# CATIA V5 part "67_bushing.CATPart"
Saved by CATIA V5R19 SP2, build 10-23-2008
Part number: 67_bushing
Bounding box of the stored display mesh (mm): x -20.495 to 20.495, y 119.884 to 160.84, z -4.564 to 26.936
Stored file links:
  C:\Documents and Settings\anizard\Bureau\13\67_bushing.CATPart
  C:\Program Files (x86)\Dassault Systemes\B19\intel_a\reffiles\standard\MetricThickPitch.txt
  C:\Documents and Settings\anizard\Bureau\13\anizard.CATProduct
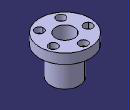
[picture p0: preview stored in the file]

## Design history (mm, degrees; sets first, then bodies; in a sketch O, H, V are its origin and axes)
Set1
  Line1: linked copy from another document
  Point1 to Point4: linked copy from another document
  Plane1 to Plane3: linked copy from another document
Body1 (main body)
  Sketch1 on yz-plane, origin (0, 0, 0), H (0, 1, 0), V (0, 0, 1)
    line L1 (160.8619, 26.936) -> (160.8619, 18.936)
    line L2 (160.8619, 18.936) -> (152.1119, 18.936)
    line L3 (152.1119, 18.936) -> (152.1119, -4.564)
    line L4 (152.1119, -4.564) -> (140.3619, -4.564)
    line L5 (160.8619, 26.936) -> (140.3619, 26.936)
    line L6 (140.3619, 26.936) -> (140.3619, -4.564)
    reference projected point E1 (152.1119, 18.936) from Point1
    reference projected point E2 (160.8619, 18.936) from Point2
    reference projected line E3 (140.3619, -341.064) -> (140.3619, 38.936) from Line1
    reference intersected line E4 through (0, 26.936) direction (-1, 0) from Plane1
    reference intersected line E5 through (0, 18.936) direction (-1, 0) from Plane2
    reference intersected line E6 through (0, -4.564) direction (-1, 0) from Plane3
    vertical: L1 V, L3 V, L6 V
    horizontal: L2 H, L4 H, L5 H
    coincidence: L3 E1, L1 E2, L6 E3, E4 L5, L2 E5, L4 E6
  Shaft1: profile Sketch1, axis Line1, angle 360
  Sketch2 on face of Shaft1 from Sketch1.L5, origin (0, 15, 26.936), H (1, 0, 0), V (0, 1, 0)
    point P1 (0, 140.3619)
    reference projected point E1 (0, 140.3619) from Point3
    coincidence: P1 E1
  Hole1: placed by Sketch2, at (0, 155.3619, 26.936) direction (0, 0, -1), diameter 4, through (limit type 6), counterbore diameter 7, counterbore depth 4.5
  CircPattern1: of Hole1, instances 6, angular step 72, axis from face of Shaft1 from Sketch1.L3
  Sketch3 on face of Shaft1 from Sketch1.L5, origin (0, 0, 26.936), H (1, 0, 0), V (0, 1, 0)
    point P1 (0, 140.3619)
    reference projected point E1 (0, 140.3619) from Point4
    coincidence: P1 E1
  Hole2: placed by Sketch3, at (0, 140.3619, 26.936) direction (0, 0, -1), diameter 15.294, through (limit type 6), threaded "M18", thread diameter 18, thread depth 31.5, pitch 2.5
